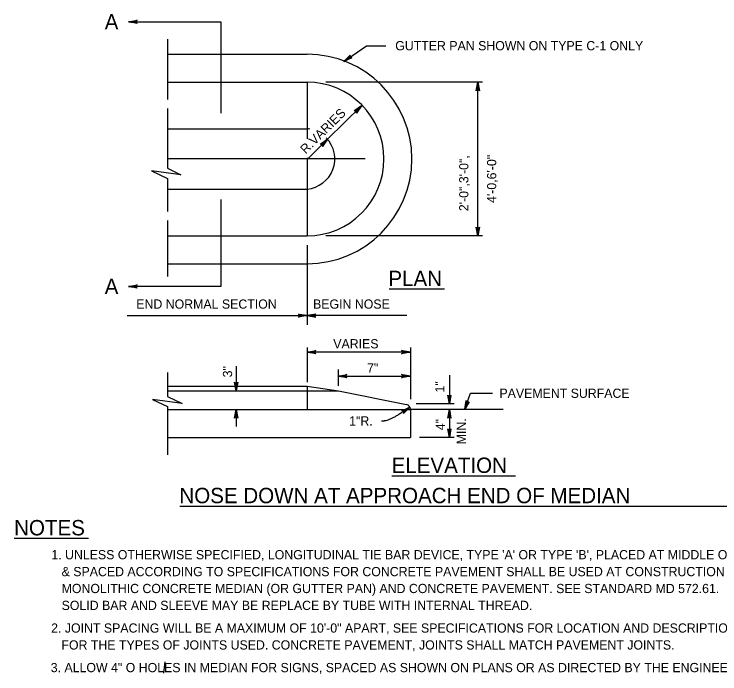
# Model space of a CAD drawing. Extents: x -28.1 to -20.9, y 67 to 77.1.
# Drawn here: x -28.073 to -23.48, y 68.52 to 72.813 of the extents above; entities that cross this region are included whole.
import ezdxf

# ---------------------------------------------------------------- set-up
doc = ezdxf.new("R2010")
doc.units = 0
for name, color, linetype in [('DETL-DIMS', 7, 'Continuous'), ('DETL-LINE', 7, 'Continuous'), ('DETL-NOTE', 7, 'Continuous'), ('DETL-TITL', 7, 'Continuous')]:
    doc.layers.add(name, color=color, linetype=linetype)

msp = doc.modelspace()

# ---------------------------------------------------------------- linework, layer by layer
at = {"layer": 'DETL-DIMS'}
for p, q in [((-27.3294, 72.7634), (-26.728, 72.7634)), ((-26.728, 72.7634), (-26.728, 72.1694)), ((-25.9272, 72.5054), (-25.7807, 72.6079)), ((-25.7807, 72.6079), (-25.6538, 72.6079)), ((-25.0261, 72.3706), (-26.0454, 72.3706)), ((-25.0564, 71.3706), (-25.0564, 72.3706)), ((-25.8136, 72.2169), (-26.0333, 71.9986)), ((-26.0333, 71.9986), (-26.1644, 71.8684)), ((-26.728, 71.6062), (-26.728, 71.0412)), ((-25.0262, 71.3706), (-26.0454, 71.3706)), ((-26.1666, 71.31), (-26.1666, 70.7907)), ((-26.728, 71.0412), (-27.3294, 71.0412)), ((-27.3381, 70.8511), (-26.1666, 70.8511)), ((-25.5176, 70.8511), (-26.1666, 70.8511)), ((-26.1666, 70.6442), (-26.1666, 70.4185)), ((-25.4948, 70.6442), (-25.4948, 70.3069)), ((-25.4948, 70.6139), (-26.1666, 70.6139)), ((-26.6275, 70.522), (-26.6275, 70.3611)), ((-25.9656, 70.5004), (-25.9656, 70.3936)), ((-25.9656, 70.458), (-25.4948, 70.458)), ((-25.2409, 70.4648), (-25.2409, 70.2762)), ((-25.141, 70.2418), (-25.1029, 70.346)), ((-25.1029, 70.346), (-24.9605, 70.346)), ((-25.2106, 70.2762), (-25.4562, 70.2762)), ((-26.6275, 70.2399), (-26.6275, 70.129)), ((-25.2409, 70.2399), (-25.2409, 70.0581)), ((-25.2106, 70.0581), (-25.4342, 70.0581))]:
    msp.add_line(p, q, dxfattribs=at)
for points in [[(-27.3294, 72.7634), (-27.2729, 72.774), (-27.2773, 72.7709), (-27.2795, 72.7672), (-27.2802, 72.7634), (-27.2795, 72.7596), (-27.2773, 72.7558), (-27.2729, 72.7528), (-27.3294, 72.7634), (-27.2773, 72.7558), (-27.2795, 72.7596), (-27.3294, 72.7634), (-27.2802, 72.7634), (-27.2795, 72.7672), (-27.3294, 72.7634), (-27.2773, 72.7709)], [(-25.9272, 72.5054), (-25.887, 72.5464), (-25.8888, 72.5415), (-25.8885, 72.5371), (-25.8868, 72.5336), (-25.8841, 72.5309), (-25.8801, 72.5291), (-25.8748, 72.5291), (-25.9272, 72.5054), (-25.8801, 72.5291), (-25.8841, 72.5309), (-25.9272, 72.5054), (-25.8868, 72.5336), (-25.8885, 72.5371), (-25.9272, 72.5054), (-25.8888, 72.5415)], [(-25.0564, 72.3706), (-25.0458, 72.3141), (-25.0488, 72.3185), (-25.0526, 72.3207), (-25.0564, 72.3214), (-25.0602, 72.3207), (-25.064, 72.3185), (-25.067, 72.3141), (-25.0564, 72.3706), (-25.064, 72.3185), (-25.0602, 72.3207), (-25.0564, 72.3706), (-25.0564, 72.3214), (-25.0526, 72.3207), (-25.0564, 72.3706), (-25.0488, 72.3185)], [(-25.8136, 72.2169), (-25.8462, 72.1695), (-25.8453, 72.1747), (-25.8464, 72.179), (-25.8486, 72.1822), (-25.8517, 72.1844), (-25.8559, 72.1855), (-25.8612, 72.1845), (-25.8136, 72.2169), (-25.8559, 72.1855), (-25.8517, 72.1844), (-25.8136, 72.2169), (-25.8486, 72.1822), (-25.8464, 72.179), (-25.8136, 72.2169), (-25.8453, 72.1747)], [(-26.0333, 71.9986), (-26.0659, 71.9513), (-26.0649, 71.9565), (-26.066, 71.9608), (-26.0682, 71.9639), (-26.0713, 71.9662), (-26.0756, 71.9673), (-26.0808, 71.9663), (-26.0333, 71.9986), (-26.0756, 71.9673), (-26.0713, 71.9662), (-26.0333, 71.9986), (-26.0682, 71.9639), (-26.066, 71.9608), (-26.0333, 71.9986), (-26.0649, 71.9565)], [(-25.0564, 71.3706), (-25.067, 71.4271), (-25.064, 71.4227), (-25.0602, 71.4205), (-25.0564, 71.4198), (-25.0526, 71.4205), (-25.0488, 71.4227), (-25.0458, 71.4271), (-25.0564, 71.3706), (-25.0488, 71.4227), (-25.0526, 71.4205), (-25.0564, 71.3706), (-25.0564, 71.4198), (-25.0602, 71.4205), (-25.0564, 71.3706), (-25.064, 71.4227)], [(-27.3294, 71.0412), (-27.2729, 71.0518), (-27.2773, 71.0488), (-27.2795, 71.045), (-27.2802, 71.0412), (-27.2795, 71.0374), (-27.2773, 71.0336), (-27.2729, 71.0306), (-27.3294, 71.0412), (-27.2773, 71.0336), (-27.2795, 71.0374), (-27.3294, 71.0412), (-27.2802, 71.0412), (-27.2795, 71.045), (-27.3294, 71.0412), (-27.2773, 71.0488)], [(-26.1666, 70.8511), (-26.2231, 70.8405), (-26.2187, 70.8435), (-26.2165, 70.8473), (-26.2159, 70.8511), (-26.2165, 70.8549), (-26.2187, 70.8587), (-26.2231, 70.8617), (-26.1666, 70.8511), (-26.2187, 70.8587), (-26.2165, 70.8549), (-26.1666, 70.8511), (-26.2159, 70.8511), (-26.2165, 70.8473), (-26.1666, 70.8511), (-26.2187, 70.8435)], [(-26.1666, 70.8511), (-26.1101, 70.8405), (-26.1145, 70.8435), (-26.1167, 70.8473), (-26.1174, 70.8511), (-26.1167, 70.8549), (-26.1145, 70.8587), (-26.1101, 70.8617), (-26.1666, 70.8511), (-26.1145, 70.8587), (-26.1167, 70.8549), (-26.1666, 70.8511), (-26.1174, 70.8511), (-26.1167, 70.8473), (-26.1666, 70.8511), (-26.1145, 70.8435)], [(-26.1666, 70.6139), (-26.1101, 70.6245), (-26.1145, 70.6215), (-26.1167, 70.6177), (-26.1174, 70.6139), (-26.1167, 70.6101), (-26.1145, 70.6063), (-26.1101, 70.6033), (-26.1666, 70.6139), (-26.1145, 70.6063), (-26.1167, 70.6101), (-26.1666, 70.6139), (-26.1174, 70.6139), (-26.1167, 70.6177), (-26.1666, 70.6139), (-26.1145, 70.6215)], [(-25.4948, 70.6139), (-25.5513, 70.6033), (-25.5469, 70.6063), (-25.5447, 70.6101), (-25.544, 70.6139), (-25.5447, 70.6177), (-25.5469, 70.6215), (-25.5513, 70.6245), (-25.4948, 70.6139), (-25.5469, 70.6215), (-25.5447, 70.6177), (-25.4948, 70.6139), (-25.544, 70.6139), (-25.5447, 70.6101), (-25.4948, 70.6139), (-25.5469, 70.6063)], [(-25.9656, 70.458), (-25.9091, 70.4686), (-25.9135, 70.4656), (-25.9157, 70.4618), (-25.9164, 70.458), (-25.9157, 70.4542), (-25.9135, 70.4505), (-25.9091, 70.4474), (-25.9656, 70.458), (-25.9135, 70.4505), (-25.9157, 70.4542), (-25.9656, 70.458), (-25.9164, 70.458), (-25.9157, 70.4618), (-25.9656, 70.458), (-25.9135, 70.4656)], [(-25.4948, 70.458), (-25.5513, 70.4474), (-25.5469, 70.4505), (-25.5447, 70.4542), (-25.544, 70.458), (-25.5447, 70.4618), (-25.5469, 70.4656), (-25.5513, 70.4686), (-25.4948, 70.458), (-25.5469, 70.4656), (-25.5447, 70.4618), (-25.4948, 70.458), (-25.544, 70.458), (-25.5447, 70.4542), (-25.4948, 70.458), (-25.5469, 70.4505)], [(-26.6275, 70.3611), (-26.6381, 70.4176), (-26.635, 70.4132), (-26.6312, 70.411), (-26.6275, 70.4103), (-26.6237, 70.411), (-26.6199, 70.4132), (-26.6169, 70.4176), (-26.6275, 70.3611), (-26.6199, 70.4132), (-26.6237, 70.411), (-26.6275, 70.3611), (-26.6275, 70.4103), (-26.6312, 70.411), (-26.6275, 70.3611), (-26.635, 70.4132)], [(-25.2409, 70.2762), (-25.2515, 70.3327), (-25.2485, 70.3283), (-25.2447, 70.3261), (-25.2409, 70.3254), (-25.2371, 70.3261), (-25.2333, 70.3283), (-25.2303, 70.3327), (-25.2409, 70.2762), (-25.2333, 70.3283), (-25.2371, 70.3261), (-25.2409, 70.2762), (-25.2409, 70.3254), (-25.2447, 70.3261), (-25.2409, 70.2762), (-25.2485, 70.3283)], [(-25.141, 70.2418), (-25.1316, 70.2985), (-25.1302, 70.2933), (-25.1274, 70.2899), (-25.1241, 70.288), (-25.1203, 70.2873), (-25.116, 70.2881), (-25.1117, 70.2912), (-25.141, 70.2418), (-25.116, 70.2881), (-25.1203, 70.2873), (-25.141, 70.2418), (-25.1241, 70.288), (-25.1274, 70.2899), (-25.141, 70.2418), (-25.1302, 70.2933)], [(-26.6275, 70.2399), (-26.6169, 70.1834), (-26.6199, 70.1877), (-26.6237, 70.19), (-26.6275, 70.1906), (-26.6312, 70.19), (-26.635, 70.1877), (-26.6381, 70.1834), (-26.6275, 70.2399), (-26.635, 70.1877), (-26.6312, 70.19), (-26.6275, 70.2399), (-26.6275, 70.1906), (-26.6237, 70.19), (-26.6275, 70.2399), (-26.6199, 70.1877)], [(-25.4988, 70.2557), (-25.539, 70.2146), (-25.5371, 70.2196), (-25.5375, 70.224), (-25.5391, 70.2274), (-25.5418, 70.2302), (-25.5458, 70.232), (-25.5511, 70.232), (-25.4988, 70.2557), (-25.5458, 70.232), (-25.5418, 70.2302), (-25.4988, 70.2557), (-25.5391, 70.2274), (-25.5375, 70.224), (-25.4988, 70.2557), (-25.5371, 70.2196)], [(-25.2409, 70.2399), (-25.2303, 70.1834), (-25.2333, 70.1877), (-25.2371, 70.19), (-25.2409, 70.1906), (-25.2447, 70.19), (-25.2485, 70.1877), (-25.2515, 70.1834), (-25.2409, 70.2399), (-25.2485, 70.1877), (-25.2447, 70.19), (-25.2409, 70.2399), (-25.2409, 70.1906), (-25.2371, 70.19), (-25.2409, 70.2399), (-25.2333, 70.1877)], [(-25.2409, 70.0581), (-25.2515, 70.1145), (-25.2485, 70.1102), (-25.2447, 70.108), (-25.2409, 70.1073), (-25.2371, 70.108), (-25.2333, 70.1102), (-25.2303, 70.1145), (-25.2409, 70.0581), (-25.2333, 70.1102), (-25.2371, 70.108), (-25.2409, 70.0581), (-25.2409, 70.1073), (-25.2447, 70.108), (-25.2409, 70.0581), (-25.2485, 70.1102)]]:
    msp.add_lwpolyline(points, dxfattribs=at)
msp.add_open_spline([(-25.4988, 70.2557), (-25.6329, 70.1582), (-25.6832, 70.1651)], degree=2, dxfattribs=at)
at = {"layer": 'DETL-LINE'}
for p, q in [((-27.0757, 72.6503), (-27.0757, 72.2571)), ((-27.0757, 72.5524), (-26.1666, 72.5524)), ((-27.0757, 72.3706), (-26.1666, 72.3706)), ((-26.1666, 72.3706), (-26.1666, 72.0007)), ((-27.0757, 72.1994), (-27.0757, 71.8107)), ((-27.0757, 72.0676), (-26.1666, 72.0676)), ((-25.7878, 71.8706), (-27.0757, 71.8706)), ((-26.1666, 71.8788), (-26.1666, 71.3706)), ((-27.0757, 71.7442), (-27.0757, 71.5283)), ((-27.0757, 71.6736), (-26.1666, 71.6736)), ((-27.0757, 71.4706), (-27.0757, 71.1051)), ((-27.0757, 71.3706), (-26.1666, 71.3706)), ((-27.0757, 71.1888), (-26.1666, 71.1888)), ((-27.0757, 70.481), (-27.0757, 70.3255)), ((-27.0757, 70.3914), (-26.1666, 70.3914)), ((-26.1666, 70.3914), (-25.9618, 70.3611)), ((-26.1666, 70.3914), (-26.1666, 70.2399)), ((-27.0757, 70.3611), (-25.9618, 70.3611)), ((-25.9618, 70.3611), (-25.5191, 70.272)), ((-27.0757, 70.2589), (-27.0757, 69.9457)), ((-27.0757, 70.2399), (-25.4948, 70.2399)), ((-25.4948, 70.2423), (-25.4948, 70.2399)), ((-25.4948, 70.2399), (-25.4948, 70.0581)), ((-24.891, 70.2399), (-25.4948, 70.2399)), ((-27.0757, 70.0581), (-25.4948, 70.0581))]:
    msp.add_line(p, q, dxfattribs=at)
for points in [[(-27.0757, 71.8107), (-26.988, 71.7678), (-27.1802, 71.7939), (-27.0757, 71.7442)], [(-27.0757, 70.3255), (-26.9797, 70.2785), (-27.1719, 70.3047), (-27.0757, 70.2589)]]:
    msp.add_lwpolyline(points, dxfattribs=at)
for centre, radius, start, end in [((-26.1666, 71.8706), 0.6818, 270, 90), ((-26.1666, 71.8706), 0.5, 270, 90), ((-26.1836, 71.8713), 0.197, 79.6169, 85.0561), ((-26.1836, 71.8713), 0.197, 274.9438, 43.9513), ((-25.5251, 70.2423), 0.0303, 0, 78.6216)]:
    msp.add_arc(centre, radius, start, end, dxfattribs=at)
at = {"layer": 'DETL-NOTE'}
for p, q in [((-28.0733, 69.4041), (-27.5887, 69.4041)), ((-27.099, 68.5252), (-27.0894, 68.5984))]:
    msp.add_line(p, q, dxfattribs=at)
at = {"layer": 'DETL-TITL'}
for p, q in [((-25.6331, 71.0246), (-25.2729, 71.0246)), ((-25.6161, 69.809), (-24.8101, 69.809)), ((-26.9957, 69.6121), (-23.4256, 69.6121))]:
    msp.add_line(p, q, dxfattribs=at)

# ---------------------------------------------------------------- texts
at = {"layer": 'DETL-NOTE'}
for s, height, p in [('GUTTER PAN SHOWN ON TYPE C-1 ONLY', 0.06, (-25.5932, 72.5779)), ('END NORMAL SECTION', 0.06, (-27.2783, 70.8965)), ('BEGIN NOSE', 0.06, (-26.1279, 70.8965)), ('VARIES', 0.06, (-25.9964, 70.6381)), ('7"', 0.06, (-25.7765, 70.4805)), ('PAVEMENT SURFACE', 0.06, (-24.915, 70.3161)), ('1"R.', 0.06, (-25.8932, 70.1359)), ('NOTES', 0.1, (-28.0733, 69.4212)), ("1. UNLESS OTHERWISE SPECIFIED, LONGITUDINAL TIE BAR DEVICE, TYPE 'A' OR TYPE 'B', PLACED AT MIDDLE OF KEYWAY", 0.06, (-27.831, 69.2656)), ('   & SPACED ACCORDING TO SPECIFICATIONS FOR CONCRETE PAVEMENT SHALL BE USED AT CONSTRUCTION JOINT BETWEEN', 0.06, (-27.831, 69.1556)), ('   MONOLITHIC CONCRETE MEDIAN (OR GUTTER PAN) AND CONCRETE PAVEMENT. SEE STANDARD MD 572.61. ', 0.06, (-27.831, 69.0456)), ('   SOLID BAR AND SLEEVE MAY BE REPLACE BY TUBE WITH INTERNAL THREAD. ', 0.06, (-27.831, 68.9356)), ('2. JOINT SPACING WILL BE A MAXIMUM OF 10\'-0" APART, SEE SPECIFICATIONS FOR LOCATION AND DESCRIPTION OF TREATMENT', 0.06, (-27.8323, 68.7883)), ('   FOR THE TYPES OF JOINTS USED. CONCRETE PAVEMENT, JOINTS SHALL MATCH PAVEMENT JOINTS.', 0.06, (-27.8323, 68.6783)), ('3. ALLOW 4" O HOLES IN MEDIAN FOR SIGNS, SPACED AS SHOWN ON PLANS OR AS DIRECTED BY THE ENGINEER.', 0.06, (-27.8349, 68.531))]:
    msp.add_text(s, height=height, dxfattribs=at).set_placement(p)
for s, rotation, p in [('R.VARIES', 44.8148, (-26.1756, 71.8998)), ('2\'-0",3\'-0",', 90, (-25.117, 71.531)), ('4\'-0,6\'-0"', 90, (-24.9358, 71.5843)), ('3"', 90, (-26.6547, 70.4497)), ('1"', 90, (-25.2728, 70.3509)), ('4"', 90, (-25.2699, 70.1056)), ('MIN.', 90, (-25.1327, 70.0141))]:
    msp.add_text(s, height=0.06, rotation=rotation, dxfattribs=at).set_placement(p)
at = {"layer": 'DETL-TITL'}
for s, p in [('A', (-27.484, 72.7134)), ('PLAN', (-25.638, 71.0432)), ('A', (-27.484, 70.9912)), ('ELEVATION', (-25.6168, 69.8276)), ('NOSE DOWN AT APPROACH END OF MEDIAN', (-26.9978, 69.6306))]:
    msp.add_text(s, height=0.1, dxfattribs=at).set_placement(p)

doc.saveas('drawing.dxf')
